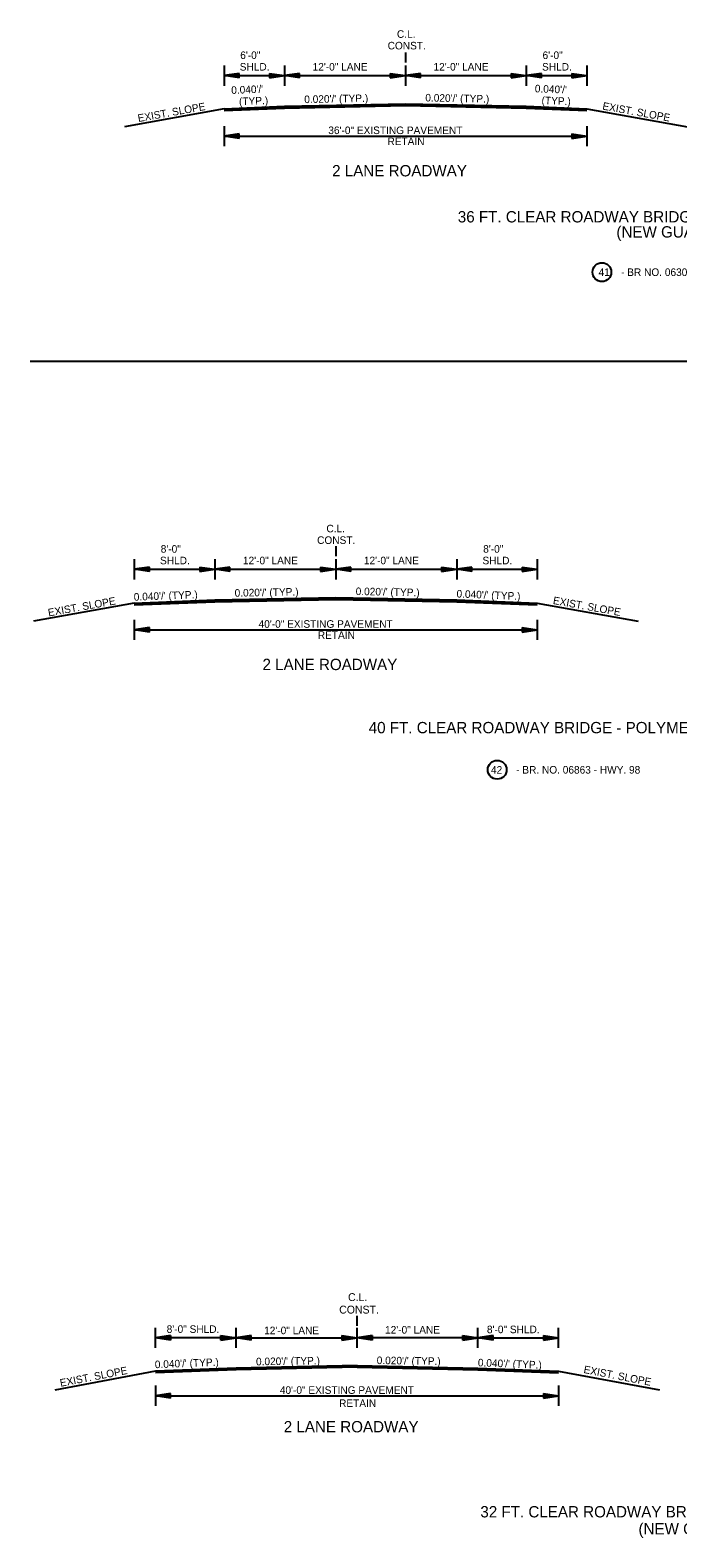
# Model space of a CAD drawing. Extents: x 545241 to 1930787, y -1971772 to 596640.
# Drawn here: x 546719 to 547362, y -1967230 to -1965733 of the extents above; entities that cross this region are included whole.
import ezdxf

# ---------------------------------------------------------------- set-up
doc = ezdxf.new("R2010")
doc.units = 0
doc.layers.add('R_Border', color=7, linetype='Continuous')
doc.layers.add('R_Draft', color=7, linetype='Continuous')

# ---------------------------------------------------------------- blocks, each defined once
blk = doc.blocks.new('ARROW')
at = {"layer": 'R_Draft'}
for p, q in [((-2, 0.3), (0, 0)), ((-2, 0.3), (-2, -0.3)), ((-2, 0.25), (-0.334, 0)), ((-2, 0.199), (-0.678, 0)), ((-2, 0.149), (-1.011, 0)), ((-2, 0.097), (-1.35, 0)), ((-2, 0.047), (-1.684, 0)), ((-2, -0.3), (0, 0)), ((-2, -0.098), (-1.35, 0)), ((-2, -0.199), (-0.678, 0)), ((-2, -0.25), (-0.334, 0)), ((-2, -0.149), (-1.011, 0)), ((-2, -0.047), (-1.684, 0))]:
    blk.add_line(p, q, dxfattribs=at)
blk = doc.blocks.new('BPPOLY')
at = {"layer": 'R_Border'}
blk.add_circle((0, 0), 9.34, dxfattribs=at)

msp = doc.modelspace()

# ---------------------------------------------------------------- linework, layer by layer
at = {"layer": 'R_Border'}
for p, q in [((547091.3, -1965755.6), (547091.3, -1965765.6)), ((546911.3, -1965768.6), (546911.3, -1965788.6)), ((546971.3, -1965768.6), (546971.3, -1965788.6)), ((547091.3, -1965768.6), (547091.3, -1965788.6)), ((547211.3, -1965768.6), (547211.3, -1965788.6)), ((547271.3, -1965768.6), (547271.3, -1965788.6)), ((546911.3, -1965778.6), (547271.3, -1965778.6)), ((546911.3, -1965811.4), (546812.4, -1965829.3)), ((547271.3, -1965811.4), (547371.3, -1965829.4)), ((546911.3, -1965828.6), (546911.3, -1965848.6)), ((547271.3, -1965828.6), (547271.3, -1965848.6)), ((546911.3, -1965838.6), (547271.3, -1965838.6)), ((546718.9, -1966062.1), (547746.9, -1966062.1)), ((547022.2, -1966245.5), (547022.2, -1966255.5)), ((546822.2, -1966258.5), (546822.2, -1966278.5)), ((546822.2, -1966268.5), (547222.2, -1966268.5)), ((546902.2, -1966258.5), (546902.2, -1966278.5)), ((547022.2, -1966258.5), (547022.2, -1966278.5)), ((547142.2, -1966258.5), (547142.2, -1966278.5)), ((547222.2, -1966258.5), (547222.2, -1966278.5)), ((546822.2, -1966302.1), (546722.2, -1966320.1)), ((547222.2, -1966302.1), (547322.2, -1966320.1)), ((546822.2, -1966318.5), (546822.2, -1966338.5)), ((546822.2, -1966328.5), (547222.2, -1966328.5)), ((547222.2, -1966318.5), (547222.2, -1966338.5)), ((546923.3, -1967061.1), (546843.3, -1967064.3)), ((546923.3, -1967061.4), (546843.3, -1967064.6)), ((546923.3, -1967061.7), (546843.3, -1967064.9)), ((546923.3, -1967062), (546843.3, -1967065.2)), ((546923.3, -1967062.3), (546843.3, -1967065.5)), ((546923.3, -1967062.6), (546843.3, -1967065.8)), ((546923.3, -1967062.7), (546843.3, -1967065.9)), ((547163.3, -1967061.1), (547243.3, -1967064.3)), ((547163.3, -1967061.4), (547243.3, -1967064.6)), ((547163.3, -1967061.7), (547243.3, -1967064.9)), ((547163.3, -1967062), (547243.3, -1967065.2)), ((547163.3, -1967062.3), (547243.3, -1967065.5)), ((547163.3, -1967062.6), (547243.3, -1967065.8)), ((547163.3, -1967062.7), (547243.3, -1967065.9))]:
    msp.add_line(p, q, dxfattribs=at)
for points in [[(546911.3, -1965811.4), (546971.3, -1965809), (547091.3, -1965806.6), (547211.3, -1965809), (547271.3, -1965811.4)], [(546911.3, -1965811.7), (546971.3, -1965809.3), (547091.3, -1965806.9), (547211.3, -1965809.3), (547271.3, -1965811.7)], [(546911.3, -1965812), (546971.3, -1965809.6), (547091.3, -1965807.2), (547211.3, -1965809.6), (547271.3, -1965812)], [(546911.3, -1965812.3), (546971.3, -1965809.9), (547091.3, -1965807.5), (547211.3, -1965809.9), (547271.3, -1965812.3)], [(546911.3, -1965812.6), (546971.3, -1965810.2), (547091.3, -1965807.8), (547211.3, -1965810.2), (547271.3, -1965812.6)], [(546911.3, -1965812.9), (546971.3, -1965810.5), (547091.3, -1965808.1), (547211.3, -1965810.5), (547271.3, -1965812.9)], [(546911.3, -1965813.2), (546971.3, -1965810.8), (547091.3, -1965808.4), (547211.3, -1965810.8), (547271.3, -1965813.2)], [(546822.2, -1966302.1), (546902.2, -1966298.9), (547022.2, -1966296.5), (547142.2, -1966298.9), (547222.2, -1966302.1)], [(546822.2, -1966302.4), (546902.2, -1966299.2), (547022.2, -1966296.8), (547142.2, -1966299.2), (547222.2, -1966302.4)], [(546822.2, -1966302.7), (546902.2, -1966299.5), (547022.2, -1966297.1), (547142.2, -1966299.5), (547222.2, -1966302.7)], [(546822.2, -1966303), (546902.2, -1966299.8), (547022.2, -1966297.4), (547142.2, -1966299.8), (547222.2, -1966303)], [(546822.2, -1966303.3), (546902.2, -1966300.1), (547022.2, -1966297.7), (547142.2, -1966300.1), (547222.2, -1966303.3)], [(546822.2, -1966303.6), (546902.2, -1966300.4), (547022.2, -1966298), (547142.2, -1966300.4), (547222.2, -1966303.6)], [(546822.2, -1966303.9), (546902.2, -1966300.7), (547022.2, -1966298.3), (547142.2, -1966300.7), (547222.2, -1966303.9)]]:
    msp.add_lwpolyline(points, dxfattribs=at)
msp.add_circle((547182.4, -1966467.4), 9.34, dxfattribs=at)
at = {"layer": 'R_Draft'}
for p, q in [((547043.3, -1967019.3), (547043.3, -1967009.3)), ((546843.3, -1967041.1), (546843.3, -1967021.1)), ((546858.3, -1967028.8), (546843.3, -1967031.1)), ((546923.3, -1967031.1), (546843.3, -1967031.1)), ((546858.3, -1967033.3), (546843.3, -1967031.1)), ((546858.3, -1967029.2), (546845.8, -1967031.1)), ((546858.3, -1967032.9), (546845.8, -1967031.1)), ((546858.3, -1967029.6), (546848.4, -1967031.1)), ((546858.3, -1967032.6), (546848.4, -1967031.1)), ((546858.3, -1967030), (546850.9, -1967031.1)), ((546858.3, -1967032.2), (546850.9, -1967031.1)), ((546858.3, -1967030.3), (546853.4, -1967031.1)), ((546858.3, -1967031.8), (546853.4, -1967031.1)), ((546858.3, -1967030.7), (546855.9, -1967031.1)), ((546858.3, -1967031.4), (546855.9, -1967031.1)), ((546858.3, -1967028.8), (546858.3, -1967033.3)), ((546908.3, -1967028.8), (546923.3, -1967031.1)), ((546908.3, -1967033.3), (546908.3, -1967028.8)), ((546908.3, -1967029.2), (546920.8, -1967031.1)), ((546908.3, -1967029.6), (546918.2, -1967031.1)), ((546908.3, -1967030), (546915.7, -1967031.1)), ((546908.3, -1967030.3), (546913.2, -1967031.1)), ((546908.3, -1967030.7), (546910.7, -1967031.1)), ((546908.3, -1967033.3), (546923.3, -1967031.1)), ((546908.3, -1967031.8), (546913.2, -1967031.1)), ((546908.3, -1967032.6), (546918.2, -1967031.1)), ((546908.3, -1967032.9), (546920.8, -1967031.1)), ((546908.3, -1967032.2), (546915.7, -1967031.1)), ((546908.3, -1967031.4), (546910.7, -1967031.1)), ((546923.3, -1967041.1), (546923.3, -1967021.2)), ((546938.3, -1967028.8), (546923.3, -1967031.1)), ((546938.3, -1967033.3), (546923.3, -1967031.1)), ((546923.3, -1967031.1), (547043.3, -1967031.1)), ((546938.3, -1967029.2), (546925.8, -1967031.1)), ((546938.3, -1967032.9), (546925.8, -1967031.1)), ((546938.3, -1967029.6), (546928.4, -1967031.1)), ((546938.3, -1967032.6), (546928.4, -1967031.1)), ((546938.3, -1967030), (546930.9, -1967031.1)), ((546938.3, -1967032.2), (546930.9, -1967031.1)), ((546938.3, -1967030.3), (546933.4, -1967031.1)), ((546938.3, -1967031.8), (546933.4, -1967031.1)), ((546938.3, -1967030.7), (546935.9, -1967031.1)), ((546938.3, -1967031.4), (546935.9, -1967031.1)), ((546938.3, -1967033.3), (546938.3, -1967028.8)), ((547028.3, -1967028.8), (547043.3, -1967031.1)), ((547028.3, -1967028.8), (547028.3, -1967033.3)), ((547028.3, -1967029.2), (547040.8, -1967031.1)), ((547028.3, -1967029.6), (547038.2, -1967031.1)), ((547028.3, -1967030), (547035.7, -1967031.1)), ((547028.3, -1967030.3), (547033.2, -1967031.1)), ((547028.3, -1967030.7), (547030.7, -1967031.1)), ((547028.3, -1967033.3), (547043.3, -1967031.1)), ((547028.3, -1967031.8), (547033.2, -1967031.1)), ((547028.3, -1967032.6), (547038.2, -1967031.1)), ((547028.3, -1967032.9), (547040.8, -1967031.1)), ((547028.3, -1967032.2), (547035.7, -1967031.1)), ((547028.3, -1967031.4), (547030.7, -1967031.1)), ((547043.3, -1967041.1), (547043.3, -1967021.2)), ((547058.3, -1967028.8), (547043.3, -1967031.1)), ((547163.3, -1967031.1), (547043.3, -1967031.1)), ((547058.3, -1967033.3), (547043.3, -1967031.1)), ((547058.3, -1967029.2), (547045.8, -1967031.1)), ((547058.3, -1967032.9), (547045.8, -1967031.1)), ((547058.3, -1967029.6), (547048.4, -1967031.1)), ((547058.3, -1967032.6), (547048.4, -1967031.1)), ((547058.3, -1967030), (547050.9, -1967031.1)), ((547058.3, -1967032.2), (547050.9, -1967031.1)), ((547058.3, -1967030.3), (547053.4, -1967031.1)), ((547058.3, -1967031.8), (547053.4, -1967031.1)), ((547058.3, -1967030.7), (547055.9, -1967031.1)), ((547058.3, -1967031.4), (547055.9, -1967031.1)), ((547058.3, -1967028.8), (547058.3, -1967033.3)), ((547148.3, -1967028.8), (547163.3, -1967031.1)), ((547148.3, -1967033.3), (547148.3, -1967028.8)), ((547148.3, -1967029.2), (547160.8, -1967031.1)), ((547148.3, -1967029.6), (547158.2, -1967031.1)), ((547148.3, -1967030), (547155.7, -1967031.1)), ((547148.3, -1967030.3), (547153.2, -1967031.1)), ((547148.3, -1967030.7), (547150.7, -1967031.1)), ((547148.3, -1967033.3), (547163.3, -1967031.1)), ((547148.3, -1967031.8), (547153.2, -1967031.1)), ((547148.3, -1967032.6), (547158.2, -1967031.1)), ((547148.3, -1967032.9), (547160.8, -1967031.1)), ((547148.3, -1967032.2), (547155.7, -1967031.1)), ((547148.3, -1967031.4), (547150.7, -1967031.1)), ((547163.3, -1967041.1), (547163.3, -1967021.2)), ((547178.3, -1967028.8), (547163.3, -1967031.1)), ((547163.3, -1967031.1), (547243.3, -1967031.1)), ((547178.3, -1967033.3), (547163.3, -1967031.1)), ((547178.3, -1967029.2), (547165.8, -1967031.1)), ((547178.3, -1967032.9), (547165.8, -1967031.1)), ((547178.3, -1967029.6), (547168.4, -1967031.1)), ((547178.3, -1967032.6), (547168.4, -1967031.1)), ((547178.3, -1967030), (547170.9, -1967031.1)), ((547178.3, -1967032.2), (547170.9, -1967031.1)), ((547178.3, -1967030.3), (547173.4, -1967031.1)), ((547178.3, -1967031.8), (547173.4, -1967031.1)), ((547178.3, -1967030.7), (547175.9, -1967031.1)), ((547178.3, -1967031.4), (547175.9, -1967031.1)), ((547178.3, -1967033.3), (547178.3, -1967028.8)), ((547228.3, -1967028.8), (547243.3, -1967031.1)), ((547228.3, -1967028.8), (547228.3, -1967033.3)), ((547228.3, -1967029.2), (547240.8, -1967031.1)), ((547228.3, -1967029.6), (547238.2, -1967031.1)), ((547228.3, -1967030), (547235.7, -1967031.1)), ((547228.3, -1967030.3), (547233.2, -1967031.1)), ((547228.3, -1967030.7), (547230.7, -1967031.1)), ((547228.3, -1967033.3), (547243.3, -1967031.1)), ((547228.3, -1967031.8), (547233.2, -1967031.1)), ((547228.3, -1967032.6), (547238.2, -1967031.1)), ((547228.3, -1967032.9), (547240.8, -1967031.1)), ((547228.3, -1967032.2), (547235.7, -1967031.1)), ((547228.3, -1967031.4), (547230.7, -1967031.1)), ((547243.3, -1967041.1), (547243.3, -1967021.1)), ((547043.3, -1967058.7), (546923.3, -1967061.1)), ((547043.3, -1967059), (546923.3, -1967061.4)), ((547043.3, -1967059.3), (546923.3, -1967061.7)), ((547043.3, -1967059.6), (546923.3, -1967062)), ((547043.3, -1967059.9), (546923.3, -1967062.3)), ((547043.3, -1967060.2), (546923.3, -1967062.6)), ((547043.4, -1967060.3), (546923.3, -1967062.7)), ((547043.3, -1967058.7), (547163.3, -1967061.1)), ((547043.3, -1967059), (547163.3, -1967061.4)), ((547043.3, -1967059.3), (547163.3, -1967061.7)), ((547043.3, -1967059.6), (547163.3, -1967062)), ((547043.3, -1967059.9), (547163.3, -1967062.3)), ((547043.3, -1967060.2), (547163.3, -1967062.6)), ((547043.3, -1967060.3), (547163.3, -1967062.7)), ((546843.3, -1967064.3), (546743.4, -1967083.1)), ((546843.3, -1967078.5), (546843.3, -1967098.5)), ((547243.3, -1967064.3), (547343.4, -1967082.7)), ((547243.3, -1967078.5), (547243.3, -1967098.5)), ((546858.3, -1967086.3), (546843.3, -1967088.5)), ((546843.3, -1967088.5), (547243.3, -1967088.5)), ((546858.3, -1967090.8), (546843.3, -1967088.5)), ((546858.3, -1967086.7), (546845.8, -1967088.5)), ((546858.3, -1967090.4), (546845.8, -1967088.5)), ((546858.3, -1967087), (546848.4, -1967088.5)), ((546858.3, -1967090), (546848.4, -1967088.5)), ((546858.3, -1967087.4), (546850.9, -1967088.5)), ((546858.3, -1967089.7), (546850.9, -1967088.5)), ((546858.3, -1967087.8), (546853.4, -1967088.5)), ((546858.3, -1967089.3), (546853.4, -1967088.5)), ((546858.3, -1967088.2), (546855.9, -1967088.5)), ((546858.3, -1967088.9), (546855.9, -1967088.5)), ((546858.3, -1967090.8), (546858.3, -1967086.3)), ((547228.3, -1967086.3), (547243.3, -1967088.5)), ((547228.3, -1967086.3), (547228.3, -1967090.8)), ((547228.3, -1967086.7), (547240.8, -1967088.5)), ((547228.3, -1967087), (547238.2, -1967088.5)), ((547228.3, -1967087.4), (547235.7, -1967088.5)), ((547228.3, -1967087.8), (547233.2, -1967088.5)), ((547228.3, -1967088.2), (547230.7, -1967088.5)), ((547228.3, -1967090.8), (547243.3, -1967088.5)), ((547228.3, -1967089.3), (547233.2, -1967088.5)), ((547228.3, -1967090), (547238.2, -1967088.5)), ((547228.3, -1967090.4), (547240.8, -1967088.5)), ((547228.3, -1967089.7), (547235.7, -1967088.5)), ((547228.3, -1967088.9), (547230.7, -1967088.5))]:
    msp.add_line(p, q, dxfattribs=at)

# ---------------------------------------------------------------- block references
at = {"layer": 'R_Border', "xscale": 7.5, "yscale": 7.5, "rotation": 180}
for p in [(546911.3, -1965778.6), (546971.3, -1965778.6), (547091.3, -1965778.6), (547211.3, -1965778.6), (546911.3, -1965838.6), (546822.2, -1966268.5), (546902.2, -1966268.5), (547022.2, -1966268.5), (547142.2, -1966268.5), (546822.2, -1966328.5)]:
    msp.add_blockref('ARROW', p, dxfattribs=at)
at = {"layer": 'R_Border', "xscale": 7.5, "yscale": 7.5}
for p in [(546971.3, -1965778.6), (547091.3, -1965778.6), (547211.3, -1965778.6), (547271.3, -1965778.6), (547271.3, -1965838.6), (546902.2, -1966268.5), (547022.2, -1966268.5), (547142.2, -1966268.5), (547222.2, -1966268.5), (547222.2, -1966328.5)]:
    msp.add_blockref('ARROW', p, dxfattribs=at)
at = {"layer": 'R_Border'}
msp.add_blockref('BPPOLY', (547286.3, -1965973.6), dxfattribs=at)

# ---------------------------------------------------------------- texts
for s, height, p in [('CONST.', 7.5, (547073.7, -1965752.6)), ('C.L.', 7.5, (547082.9, -1965741.1)), ('6\'-0"', 7.5, (546927.4, -1965762.1)), ('6\'-0"', 7.5, (547227.4, -1965762.1)), ('SHLD.', 7.5, (546926.9, -1965773.6)), ('12\'-0" LANE', 7.5, (546999.2, -1965773.6)), ('12\'-0" LANE', 7.5, (547119.2, -1965773.6)), ('SHLD.', 7.5, (547226.9, -1965773.6)), ('36\'-0" EXISTING PAVEMENT', 7.5, (547014.8, -1965836.6)), ('RETAIN', 7.5, (547073.5, -1965847.6)), ('2 LANE ROADWAY', 11.25, (547018.6, -1965878.6)), ('36 FT. CLEAR ROADWAY BRIDGE - POLYMER OVERLAY', 11.25, (547143.3, -1965924.3)), ('(NEW GUARDRAIL)', 11.25, (547300.7, -1965939.3)), ('41', 7.5, (547283, -1965977.4)), ('- BR NO. 06303 - HWY. 63', 7.5, (547305.3, -1965977.4)), ('C.L.', 7.5, (547012.9, -1966231.8)), ('CONST.', 7.5, (547003.7, -1966243.3)), ('SHLD.', 7.5, (546847.8, -1966263.5)), ('8\'-0"', 7.5, (546848.5, -1966252)), ('12\'-0" LANE', 7.5, (546930.1, -1966263.5)), ('12\'-0" LANE', 7.5, (547050.1, -1966263.5)), ('SHLD.', 7.5, (547167.8, -1966263.5)), ('8\'-0"', 7.5, (547168.5, -1966252)), ('40\'-0" EXISTING PAVEMENT', 7.5, (546945.6, -1966326.5)), ('RETAIN', 7.5, (547004.4, -1966337.5)), ('2 LANE ROADWAY', 11.25, (546949.5, -1966368.5)), ('40 FT. CLEAR ROADWAY BRIDGE - POLYMER OVERLAY', 11.25, (547054.9, -1966431.2))]:
    msp.add_text(s, height=height, dxfattribs=at).set_placement(p)
for s, rotation, p in [("0.040'/' ", 2.2916, (546918.6, -1965796.8)), ("0.040'/'", 357.7084, (547219.6, -1965795.1)), ('EXIST. SLOPE', 10.204, (546826.4, -1965824.7)), ('(TYP.)', 2.2916, (546926.3, -1965808)), ("0.020'/' (TYP.)", 1.1458, (546991, -1965805.9)), ("0.020'/' (TYP.)", 358.8542, (547111, -1965804.2)), ('(TYP.)', 357.7084, (547226.3, -1965806.8)), ('EXIST. SLOPE', 349.796, (547286.4, -1965812.2)), ('EXIST. SLOPE', 10.204, (546737.3, -1966315.3)), ("0.040'/' (TYP.)", 2.2916, (546821.9, -1966299.7)), ("0.020'/' (TYP.)", 1.1458, (546921.9, -1966295.7)), ("0.020'/' (TYP.)", 358.8542, (547041.9, -1966294)), ("0.040'/' (TYP.)", 357.7084, (547141.9, -1966296.4)), ('EXIST. SLOPE', 349.796, (547237.3, -1966302.8))]:
    msp.add_text(s, height=7.5, rotation=rotation, dxfattribs=at).set_placement(p)
at = {"layer": 'R_Draft'}
for s, height, p in [('42', 7.5, (547176.2, -1966471.3)), ('- BR. NO. 06863 - HWY. 98', 7.5, (547201.2, -1966471.2)), ('C.L.', 7.8, (547034.4, -1966994.6)), ('CONST.', 7.8, (547025.6, -1967007)), ('8\'-0" SHLD.', 7.5, (546854.4, -1967026.2)), ('8\'-0" SHLD.', 7.5, (547172.2, -1967026.5)), ('12\'-0" LANE', 7.5, (546951.1, -1967027.5)), ('12\'-0" LANE', 7.5, (547071.1, -1967026.9)), ('40\'-0" EXISTING PAVEMENT', 7.5, (546966.7, -1967086.7)), ('RETAIN', 7.5, (547025.5, -1967099.7)), ('2 LANE ROADWAY', 11.25, (546970.6, -1967124.9)), ('32 FT. CLEAR ROADWAY BRIDGE - POLYMER OVERLAY', 11.25, (547165.7, -1967209.3)), ('(NEW GUARDRAIL)', 11.25, (547322.6, -1967226.2))]:
    msp.add_text(s, height=height, dxfattribs=at).set_placement(p)
for s, rotation, p in [('EXIST. SLOPE', 10.8829, (546749.2, -1967079.7)), ("0.040'/' (TYP.)", 2.2906, (546842.8, -1967061.3)), ("0.020'/' (TYP.)", 0.8719, (546943.1, -1967058.4)), ("0.020'/' (TYP.)", 359.1281, (547062.8, -1967057.1)), ("0.040'/' (TYP.)", 357.7094, (547163.1, -1967059.3)), ('EXIST. SLOPE', 349.1171, (547267.7, -1967065.9))]:
    msp.add_text(s, height=7.5, rotation=rotation, dxfattribs=at).set_placement(p)

doc.saveas('drawing.dxf')
